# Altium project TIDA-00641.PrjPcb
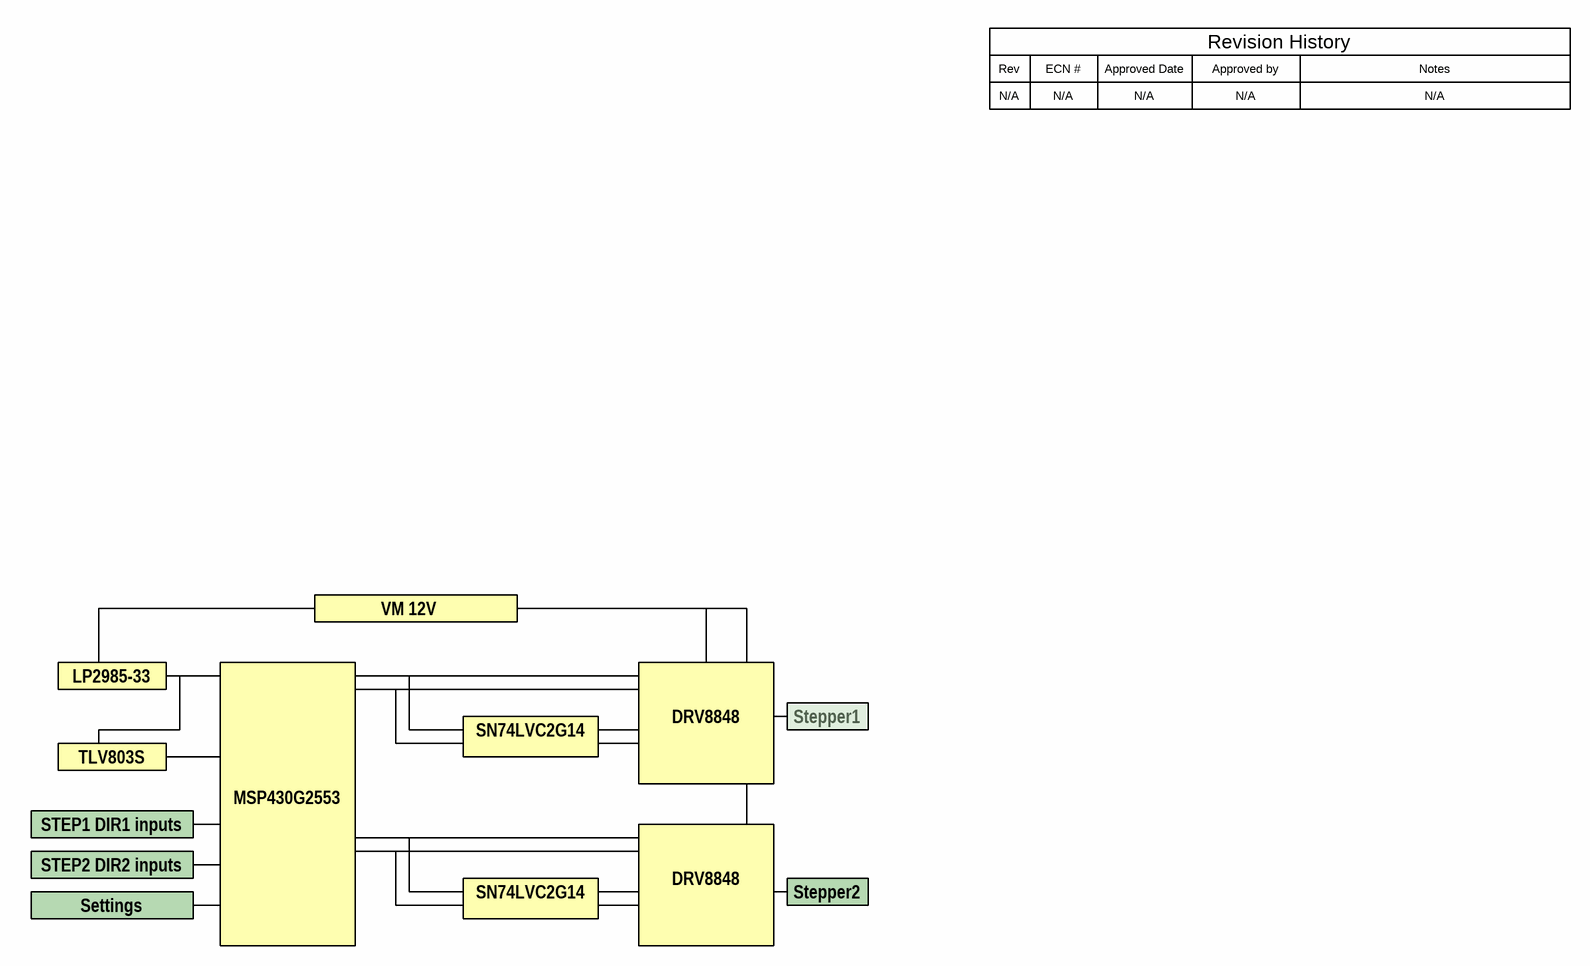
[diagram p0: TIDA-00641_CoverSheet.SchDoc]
CopyrightYear: 2015; EVM_Orderable: N/A; PCB_Layout: Wilson Zuo; PCB_Rev: Rev A; PRJ_Customer: Public Release; PRJ_Engineer: Wilson Zuo; PRJ_Number: TIDA-00641; PRJ_Title: Dual Channels PWM Micro-stepping Module; SCH_Rev: E1; TechSupport: http://www.ti.com/support; TID: 00641
3 sheets, 48 parts. Net scope: global (net labels, ports and power ports of the same name join across sheets).
Board file: TIDA-00641_PCB.PcbDoc
Sheets:
  TIDA-00641_CoverSheet.SchDoc
  TIDA-00641_SCH.SchDoc
  TIDA-00641_Hardware.SchDoc

## Sheet TIDA-00641_CoverSheet.SchDoc
size 431 x 279 mm; Date: Not shown in title block; ApprovedBy: Not shown in title block; CheckedBy: Not shown in title block; Author: Not shown in title block; CompanyName: Not shown in title block; Engineer: Not shown in title block; Organization: Not shown in title block; Address1: Not shown in title block; Address2: Not shown in title block; Address3: Not shown in title block; Address4: Not shown in title block; DocumentNumber: 1; Revision: Use project parameter SCH_Rev; SheetNumber: 1; SheetTotal: 3; PageSetup: Record=PageOptions¦CenterHorizontal=True¦CenterVertical=True¦PrintScale=1.00¦XCorrection=1.00¦YCorrection=1.00¦PrintKind=0¦BorderSize=5000000¦LeftOffset=0¦BottomOffset=0¦Orientation=2¦PaperLength=1000¦PaperWidth=1000¦Scale=100¦PaperSource=15¦PrintQuality=600¦MediaType=1¦DitherType=10¦PaperKind=Letter¦PrintScaleMode=1

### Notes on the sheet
- Rev
- N/A
- ECN #
- Approved Date
- Approved by
- Revision History
- Notes
- VM 12V
- LP2985-33
- TLV803S
- SN74LVC2G14
- DRV8848
- Stepper1
- STEP1 DIR1 inputs
- MSP430G2553
- STEP2 DIR2 inputs
- Settings
- Stepper2

## Sheet TIDA-00641_SCH.SchDoc
size 431 x 279 mm; Date: Not shown in title block; ApprovedBy: Not shown in title block; CheckedBy: Not shown in title block; Author: Not shown in title block; CompanyName: Not shown in title block; Engineer: Not shown in title block; Organization: Not shown in title block; Address1: Not shown in title block; Address2: Not shown in title block; Address3: Not shown in title block; Address4: Not shown in title block; DocumentNumber: 1; Revision: Use project parameter SCH_Rev; SheetNumber: 2; SheetTotal: 3; PageSetup: Record=PageOptions¦CenterHorizontal=True¦CenterVertical=True¦PrintScale=1.00¦XCorrection=1.00¦YCorrection=1.00¦PrintKind=0¦BorderSize=5000000¦LeftOffset=0¦BottomOffset=0¦Orientation=2¦PaperLength=1000¦PaperWidth=1000¦Scale=100¦PaperSource=15¦PrintQuality=600¦MediaType=1¦DitherType=10¦PaperKind=Letter¦PrintScaleMode=1
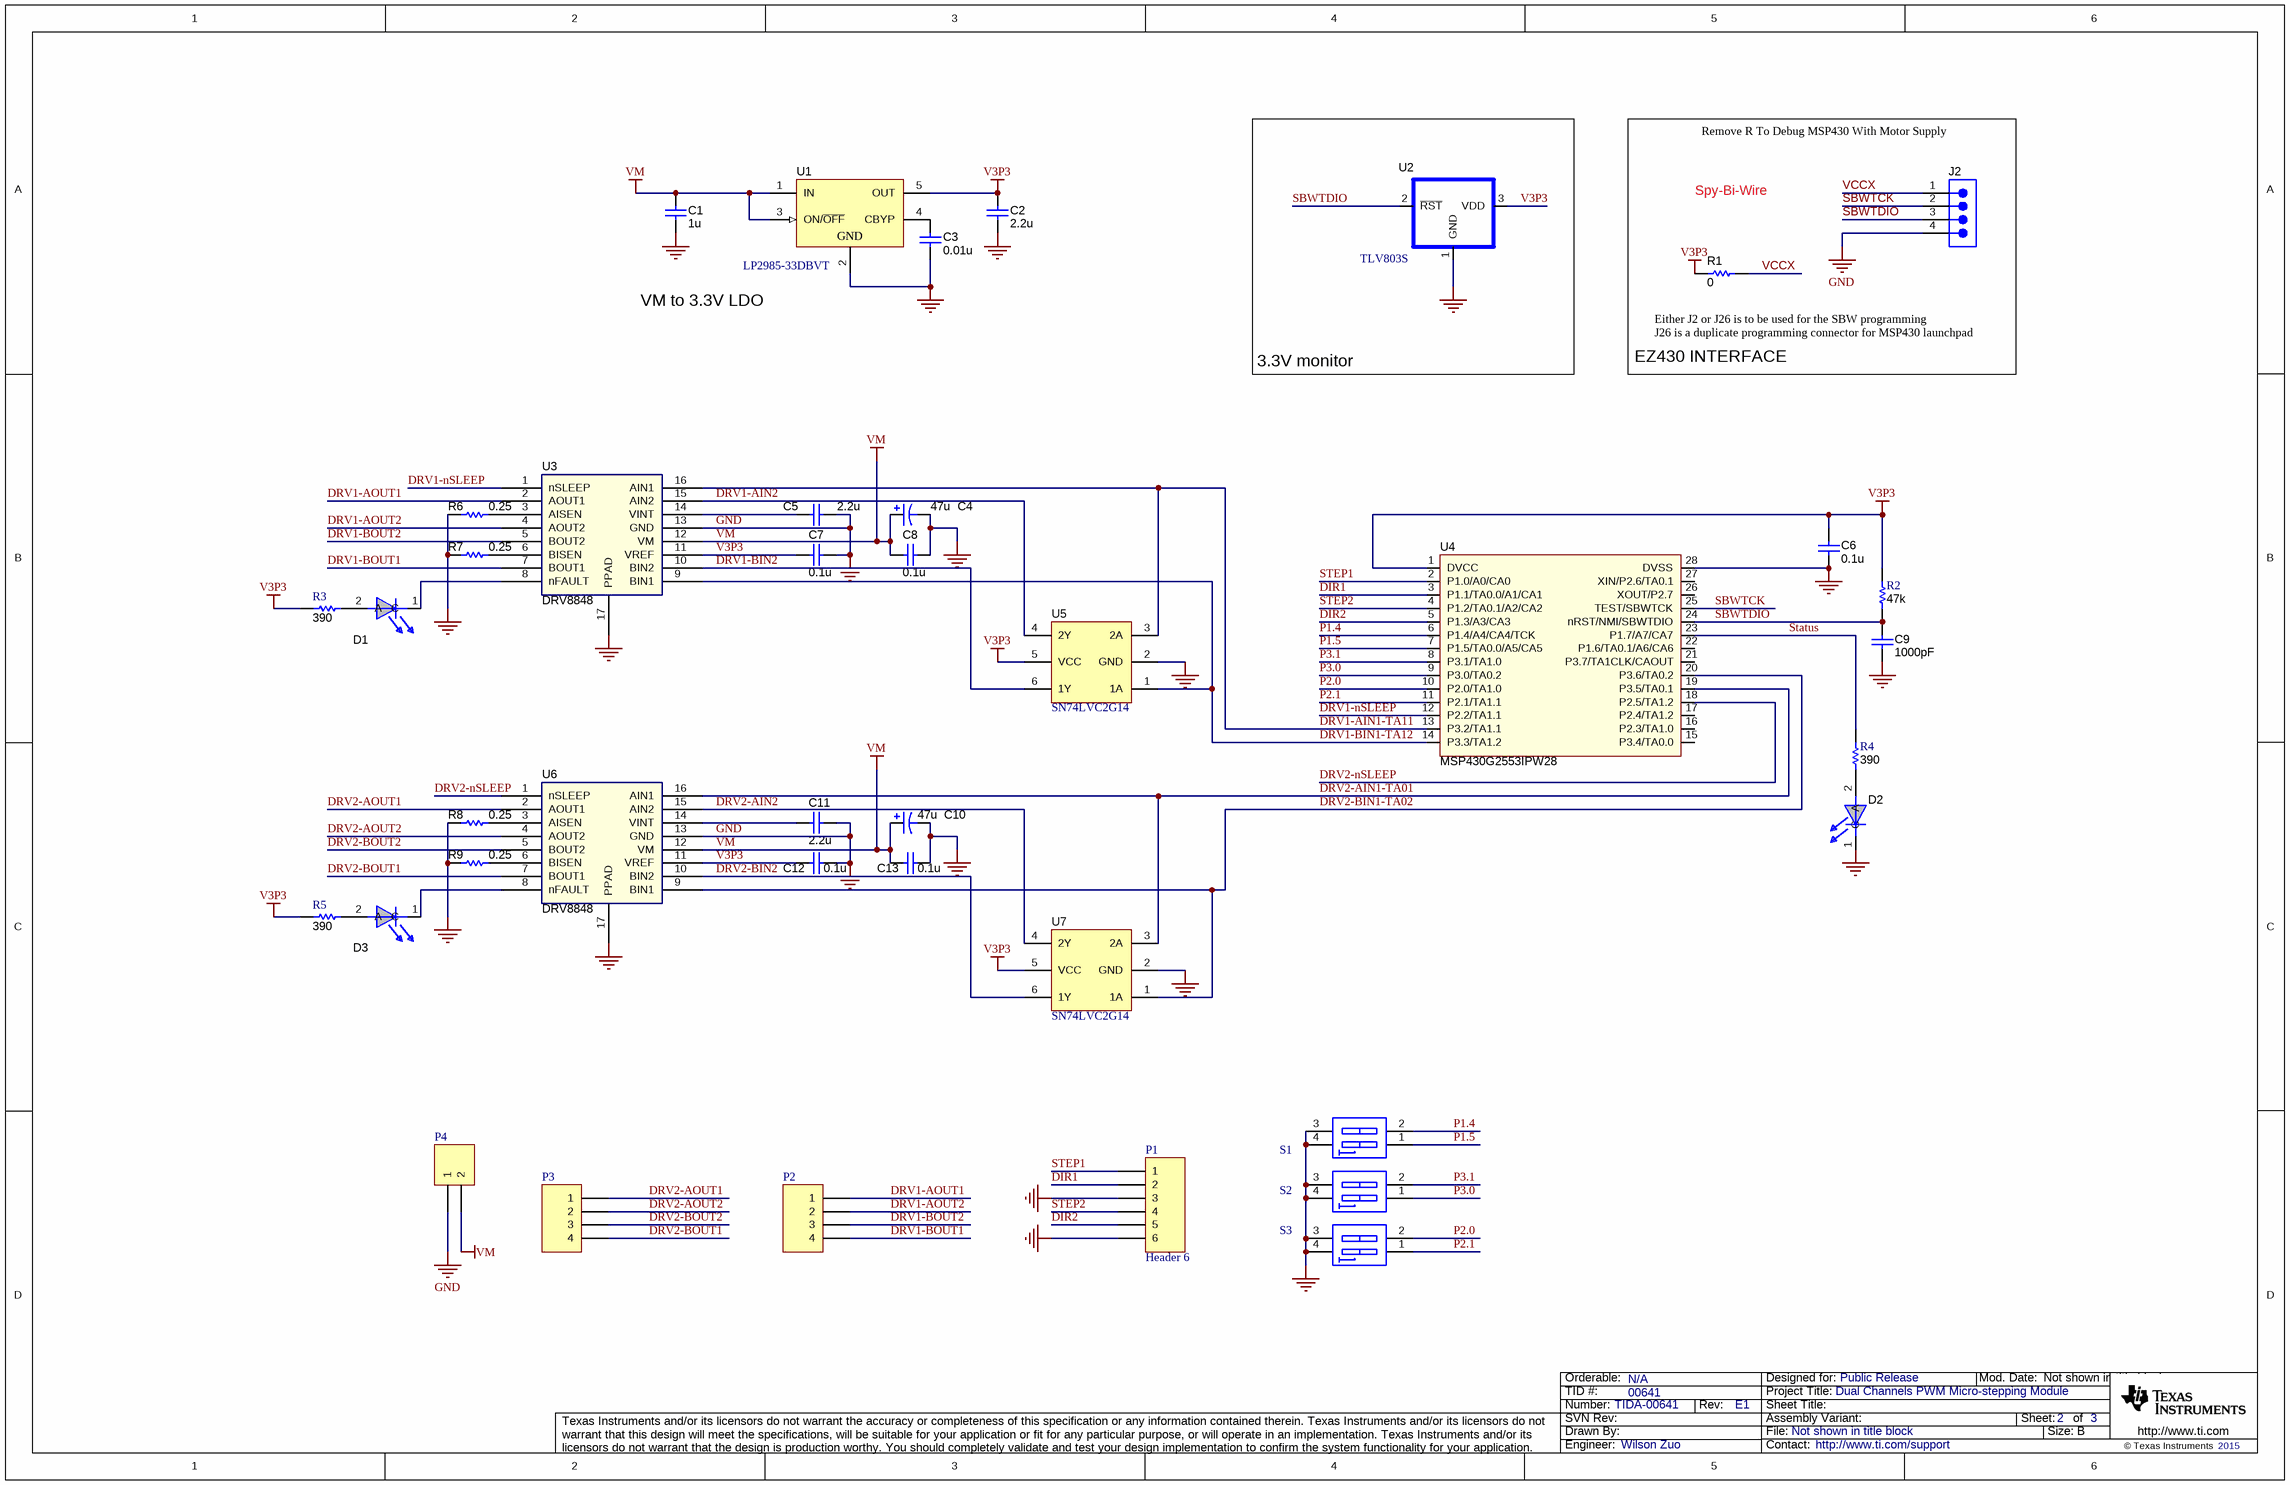
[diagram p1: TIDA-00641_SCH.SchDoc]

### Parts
C1  ValueDisplayed: 1u  [0603L]  (hidden comment: C0603C105K4PACTU)
C2  ValueDisplayed: 2.2u  [0603L]  (hidden comment: C0603C225K8PACTU)
C3  ValueDisplayed: 0.01u  [0603L]  (hidden comment: C0603C103J5RACTU)
C4  ValueDisplayed: 47u  [SM_RADIAL_D]  (hidden comment: EEE-FK1E470P)
C5  ValueDisplayed: 2.2u  [0603L]  (hidden comment: C0603C225M8PACTU)
C6  ValueDisplayed: 0.1u  [0603L]  (hidden comment: C0603C104K4RACTU)
C7  ValueDisplayed: 0.1u  [0603L]  (hidden comment: 06033C104KAT2A)
C8  ValueDisplayed: 0.1u  [0603L]  (hidden comment: 06033C104KAT2A)
C9  ValueDisplayed: 1000pF  [0603L]  (hidden comment: C0603C102K5RACTU)
C10  ValueDisplayed: 47u  [SM_RADIAL_D]  (hidden comment: EEE-FK1E470P)
C11  ValueDisplayed: 2.2u  [0603L]  (hidden comment: C0603C225K8PACTU)
C12  ValueDisplayed: 0.1u  [0603L]  (hidden comment: 06033C104KAT2A)
C13  ValueDisplayed: 0.1u  [0603L]  (hidden comment: 06033C104KAT2A)
D1  LTST-C190KRKT  [LED603RED]  (value not drawn)
D2  LTST-C190GKT  [LED603GRN]  (value not drawn)
D3  LTST-C190KRKT  [LED603RED]  (value not drawn)
J2  TSW-104-07-G-S  [HDR1X4]  (value not drawn)
P1  Header 6  [HDR1X6]
P2  Header 4  [J4-3.81]  (value not drawn)
P3  Header 4  [J4-3.81]  (value not drawn)
P4  Header 2  [j2-3.81]  (value not drawn)
R1  value 0  [0603L]  (hidden comment: ERJ-3GEY0R00V)
R2  value 47k  [0603L]  (hidden comment: CRCW060347K0JNEA)
R3  value 390  [0603L]  (hidden comment: RC0603FR-07390RL)
R4  value 390  [0603L]  (hidden comment: RC0603FR-07390RL)
R5  value 390  [0603L]  (hidden comment: RC0603FR-07390RL)
R6  value 0.25  [2512M]  (hidden comment: CSRN2512FKR250)
R7  value 0.25  [2512M]  (hidden comment: CSRN2512FKR250)
R8  value 0.25  [2512M]  (hidden comment: CSRN2512FKR250)
R9  value 0.25  [2512M]  (hidden comment: CSRN2512FKR250)
S1  SW DIP-2  [DIP-4]  (value not drawn)
S2  SW DIP-2  [DIP-4]  (value not drawn)
S3  SW DIP-2  [DIP-4]  (value not drawn)
U1  LP2985-33DBVT  [MF05A_L]
U2  TLV803S  [SOT-23]
U3  DRV8848  [PW0016S]
U4  MSP430G2553IPW28  [PW0028A_N]
U5  SN74LVC2G14  [DBV0006A_N]
U6  DRV8848  [PW0016S]
U7  SN74LVC2G14  [DBV0006A_N]

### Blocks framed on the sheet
3.3V monitor: U2
EZ430 INTERFACE: J2 R1

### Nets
GND: C1.2 C2.1 C3.2 C4.2(-) C5.2 C6.1 C7.1 C8.1 C9.1 C10.2(-) C11.2 C12.1 C13.1 D2.1(C) J2.4 P1.3 P1.6 P4.1 R6.1 R7.1 R8.1 R9.1 S1.3(B2) S1.4(B1) S2.3(B2) S2.4(B1) S3.3(B2) S3.4(B1) U1.2(GND) U2.1(GND) U3.13(GND) U3.17(PPAD) U4.28(DVSS) U5.2(GND) U6.13(GND) U6.17(PPAD) U7.2(GND)
V3P3: C2.2 C6.2 C7.2 C12.2 R1.1 R2.1 R3.2 R5.2 U1.5(OUT) U2.3(VDD) U3.11(VREF) U4.1(DVCC) U5.5(VCC) U6.11(VREF) U7.5(VCC)
VM: C1.1 C4.1(+) C8.2 C10.1(+) C13.2 P4.2 U1.1(IN) U1.3(ON/~{OFF}) U3.12(VM) U6.12(VM)
DIR1: P1.2 U4.3(P1.1/TA0.0/A1/CA1)
DIR2: P1.5 U4.5(P1.3/A3/CA3)
DRV1-AIN1-TA11: U3.16(AIN1) U4.13(P3.2/TA1.1) U5.3(2A)
DRV1-AIN2: U3.15(AIN2) U5.4(2Y)
DRV1-AOUT1: P2.1 U3.2(AOUT1)
DRV1-AOUT2: P2.2 U3.4(AOUT2)
DRV1-BIN1-TA12: U3.9(BIN1) U4.14(P3.3/TA1.2) U5.1(1A)
DRV1-BIN2: U3.10(BIN2) U5.6(1Y)
DRV1-BOUT1: P2.4 U3.7(BOUT1)
DRV1-BOUT2: P2.3 U3.5(BOUT2)
DRV1-nSLEEP: U3.1(nSLEEP) U4.12(P2.2/TA1.1)
DRV2-AIN1-TA01: U4.19(P3.5/TA0.1) U6.16(AIN1) U7.3(2A)
DRV2-AIN2: U6.15(AIN2) U7.4(2Y)
DRV2-AOUT1: P3.1 U6.2(AOUT1)
DRV2-AOUT2: P3.2 U6.4(AOUT2)
DRV2-BIN1-TA02: U4.20(P3.6/TA0.2) U6.9(BIN1) U7.1(1A)
DRV2-BIN2: U6.10(BIN2) U7.6(1Y)
DRV2-BOUT1: P3.4 U6.7(BOUT1)
DRV2-BOUT2: P3.3 U6.5(BOUT2)
DRV2-nSLEEP: U4.18(P2.5/TA1.2) U6.1(nSLEEP)
P1.4: S1.2(A2) U4.6(P1.4/A4/CA4/TCK)
P1.5: S1.1(A1) U4.7(P1.5/TA0.0/A5/CA5)
P2.0: S3.2(A2) U4.10(P2.0/TA1.0)
P2.1: S3.1(A1) U4.11(P2.1/TA1.1)
P3.0: S2.1(A1) U4.9(P3.0/TA0.2)
P3.1: S2.2(A2) U4.8(P3.1/TA1.0)
SBWTCK: J2.2 U4.25(TEST/SBWTCK)
SBWTDIO: C9.2 J2.3 R2.2 U2.2(~{RST}) U4.24(nRST/NMI/SBWTDIO)
Status: R4.2 U4.23(P1.7/A7/CA7)
STEP1: P1.1 U4.2(P1.0/A0/CA0)
STEP2: P1.4 U4.4(P1.2/TA0.1/A2/CA2)
VCCX: J2.1 R1.2
NetC3_1: C3.1 U1.4(CBYP)
NetC5_1: C5.1 U3.14(VINT)
NetC11_1: C11.1 U6.14(VINT)
NetD1_1: D1.1(C) U3.8(nFAULT)
NetD1_2: D1.2(A) R3.1
NetD2_2: D2.2(A) R4.1
NetD3_1: D3.1(C) U6.8(nFAULT)
NetD3_2: D3.2(A) R5.1
NetR6_2: R6.2 U3.3(AISEN)
NetR7_2: R7.2 U3.6(BISEN)
NetR8_2: R8.2 U6.3(AISEN)
NetR9_2: R9.2 U6.6(BISEN)

Not connected (* = marked no-connect by the designer): U4 15(P3.4/TA0.0) 16(P2.3/TA1.0) 17(P2.4/TA1.2) 21(P3.7/TA1CLK/CAOUT) 22(P1.6/TA0.1/A6/CA6) 26(XOUT/P2.7) 27(XIN/P2.6/TA0.1)

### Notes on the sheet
- Remove R To Debug MSP430 With Motor Supply
- Spy-Bi-Wire
- VM to 3.3V LDO
- (near R1) Either J2 or J26 is to be used for the SBW programming
- J26 is a duplicate programming connector for MSP430 launchpad

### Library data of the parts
C1 = C0603C105K4PACTU: CAP, CERM, 1uF, 16V, +/-10%, X5R, 0603; Manufacturer: Kemet; Polarized: N; CompType: Capacitor; U/M: EA; Cap_F: 0.000001; Tolerance_%: 10; Value1: Unknown; VDC_V: 16; TaMin_C: -55; TaMax_C: 85; Cap_Case: 0603
C2 C11 = C0603C225K8PACTU: CAP, CERM, 2.2uF, 10V, +/-10%, X5R, 0603; Manufacturer: Kemet; Polarized: N; CompType: Capacitor; U/M: EA; Cap_F: 0.0000022; Tolerance_%: 10; Value1: Unknown; TaMin_C: -55; TaMax_C: 85; Cap_Case: 0603
C3 = C0603C103J5RACTU: CAP, CERM, 0.01uF, 50V, +/-5%, X7R, 0603; Manufacturer: Kemet; Polarized: N; CompType: Capacitor; U/M: EA; Cap_F: 0.00000001; Tolerance_%: 5; Value1: Unknown; VDC_V: 50; TaMin_C: -55; TaMax_C: 125; Cap_Case: 0603
C4 C10 = EEE-FK1E470P: CAP, AL, 47uF, 25V, +/-20%, 0.36 ohm, SMD; Manufacturer: Panasonic; Polarized: Y; CompType: Capacitor; U/M: EA; Cap_F: 0.000047; Tolerance_%: 20; ESR_Ohm: 0.36; VDC_V: 25; IRMS_A: 0.24; TaMin_C: -55; TaMax_C: 105; Cap_Case: D
C5 = C0603C225M8PACTU: CAP, CERM, 2.2uF, 10V, +/-20%, X5R, 0603; Manufacturer: Kemet; Polarized: N; CompType: Capacitor; U/M: EA; Cap_F: 0.0000022; Tolerance_%: 20; Value1: Unknown; VDC_V: 10; TaMin_C: -55; TaMax_C: 85; Cap_Case: 0603
C6 = C0603C104K4RACTU: CAP, CERM, 0.1uF, 16V, +/-10%, X7R, 0603; Manufacturer: Kemet; Polarized: N; CompType: Capacitor; U/M: EA; Cap_F: 0.0000001; Tolerance_%: 10; Value1: Unknown; VDC_V: 16; TaMin_C: -55; TaMax_C: 125; Cap_Case: 0603
C7 C8 C12 C13 = 06033C104KAT2A: CAP, CERM, 0.1uF, 25V, +/-10%, X7R, 0603; Manufacturer: AVX; Polarized: N; CompType: Capacitor; U/M: EA; Cap_F: 0.0000001; Tolerance_%: 10; ESR_Ohm: 0.05; Value1: 0.05 ohm; VDC_V: 25; TaMin_C: -55; TaMax_C: 125; Cap_Case: 0603
C9 = C0603C102K5RACTU: CAP, CERM, 1000pF, 50V, +/-10%, X7R, 0603; Manufacturer: Kemet; Polarized: N; CompType: Capacitor; U/M: EA; Cap_F: 0.000000001; Tolerance_%: 10; Value1: Unknown; VDC_V: 50; TaMin_C: -55; TaMax_C: 125; Cap_Case: 0603
D1 D3 = D_LED_603_GRN: LED SUPER RED CLEAR 0603 SMD; Manufacturer: Lite On; Value: LTST-C190GKT; Area: 9451
D2 = D_LED_603_GRN: Diode, LED, Green, 2.1-V, 20-mA, 6-mcd; Manufacturer: Lite On; Area: 9451
J2 = TSW-104-07-G-S: Header, TH, 100mil, 4x1, Gold plated, 230 mil above insulator; Manufacturer: Samtec, Inc.; SymbolCreator: a0412235; U/M: EA
P1 = Header 6: Header, 6-Pin
P2 P3 = Header 4: Header, 4-Pin
P4 = Header 2: Header, 2-Pin
R1 = ERJ-3GEY0R00V: RES, 0 ohm, 5%, 0.1W, 0603; Manufacturer: Panasonic; CompType: Resistor; Value_Code: 0000; Tolerance_%: 5; Power_W: 0.1; VDC_V: 50; TempCo: 600 ppm/C; EIA_Code: E24; U/M: EA
R2 = CRCW060347K0JNEA: RES, 47k ohm, 5%, 0.1W, 0603; Manufacturer: Vishay-Dale; CompType: Resistor; Res_ohm: 47000; Value_Code: 47k0; Tolerance_%: 5; Power_W: 0.1; VDC_V: 75; TempCo: 200 ppm/C; EIA_Code: E24; U/M: EA
R3-R5 = RC0603FR-07390RL: RES, 390 ohm, 1%, 0.1W, 0603; Manufacturer: Yageo America; CompType: Resistor; Value_Code: 390R; Tolerance_%: 1; Power_W: 0.1; VDC_V: 150; TempCo: 200 ppm/C; U/M: EA
R6-R9 = CSRN2512FKR250: RES, 0.25 ohm, 1%, 2W, 2512; Manufacturer: Stackpole Electronics Inc; CompType: Resistor; Value_Code: R250; Tolerance_%: 1; Power_W: 2; TempCo: 200 ppm/C; U/M: EA
S1-S3 = SW DIP-2: SWITCH TIN CONT 2 SEC 50V
U1 = LP2985IM5-3.3: Micropower 150 mA Low-Noise Ultra Low-Dropout Regulator, 5-pin SOT-23; Manufacturer: National Semiconductor; PackageTopMarking: L0RB*XTT; PowerWise: N; CompType: LDO IC
U2 = TLV803DBZ: IC VOLT SUPERVISR 2.93V SOT23-3; Manufacturer: TI; PartNumber: TLV803SDBZR; Alternate Manufacturer: None; Area: 28050; Value: TLV803xDBZ
U3 U6 = DRV8848PWP: IC MOTOR DRIVER PAR 16HTSSOP; Manufacturer: Used in BOM report; Manufacturer: Texas Instruments; SymbolVersion: use current date i.e. 2008-05-20; SymbolCreator: Use a-id; CompType: Used in some BOM reports.  Useful for finding later.; U/M: EA, IN, or GM
U4 = MSP430G2553IPW28: IC MCU 16BIT 16KB FLASH 28TSSOP; Manufacturer: TI; Alternate Manufacturer: None; Area: 92800
U5 U7 = SN74LVC2G14: Dual Schmitt-Trigger Inverter; Manufacturer: Texas Instruments; PartNumber: SN74LVC2G14DBVR

## Sheet TIDA-00641_Hardware.SchDoc
size 431 x 279 mm; Date: Not shown in title block; ApprovedBy: Not shown in title block; CheckedBy: Not shown in title block; Author: Not shown in title block; CompanyName: Not shown in title block; Engineer: Not shown in title block; Organization: Not shown in title block; Address1: Not shown in title block; Address2: Not shown in title block; Address3: Not shown in title block; Address4: Not shown in title block; DocumentNumber: 1; Revision: Use project parameter SCH_Rev; SheetNumber: 3; SheetTotal: 3; PageSetup: Record=PageOptions¦CenterHorizontal=True¦CenterVertical=True¦PrintScale=1.00¦XCorrection=1.00¦YCorrection=1.00¦PrintKind=0¦BorderSize=5000000¦LeftOffset=0¦BottomOffset=0¦Orientation=2¦PaperLength=1000¦PaperWidth=1000¦Scale=100¦PaperSource=15¦PrintQuality=600¦MediaType=1¦DitherType=10¦PaperKind=Letter¦PrintScaleMode=1
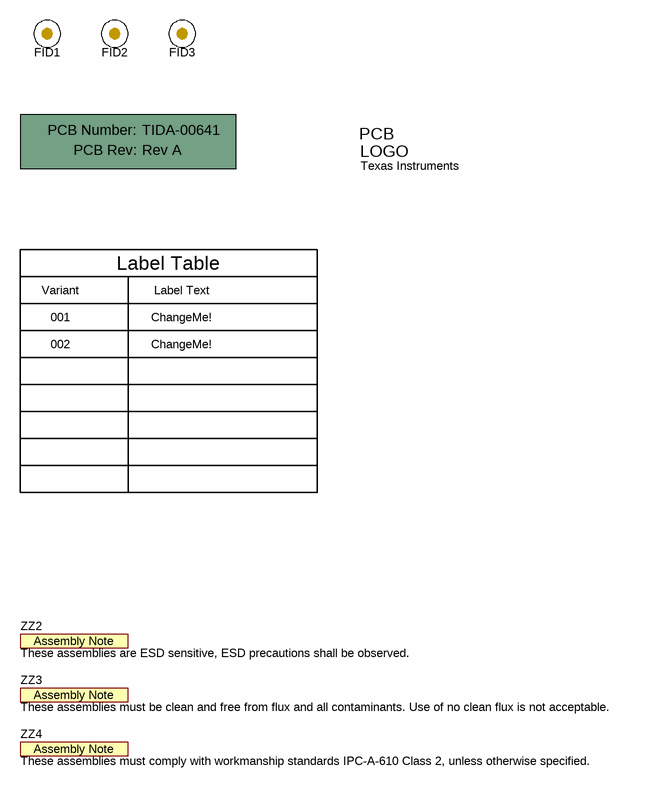
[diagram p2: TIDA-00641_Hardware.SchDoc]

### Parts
!PCB  Printed Circuit Board  (value not drawn)  (mechanical)
FID1  Fiducial  [Fiducial10-20]  (value not drawn)
FID2  Fiducial  [Fiducial10-20]  (value not drawn)
FID3  Fiducial  [Fiducial10-20]  (value not drawn)
Logo1  Texas Instruments  [TI_Stacked_Overlay_Small]  (no BOM)
ZZ2  These assemblies are ESD sensitive, ESD precautions shall be observed.  [AssemblyNote]  (no BOM)
ZZ3  These assemblies must be clean and free from flux and all contaminants. Use of no clean flux is not acceptable.  [AssemblyNote]  (no BOM)
ZZ4  These assemblies must comply with workmanship standards IPC-A-610 Class 2, unless otherwise specified.  [AssemblyNote]  (no BOM)

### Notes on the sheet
- Variant
- Label Table
- Label Text
- 001
- 002
- ChangeMe!

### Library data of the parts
!PCB = PCB: Manufacturer: Any; PartNumber: TIDA-00641; SymbolCreator: a0412235
FID1-FID3 = Fiducial: Fiducial mark.  There is nothing to buy or mount.; SymbolCreator: codlsc
Logo1 = TI_Logo: Texas Instrument Corporate Signature; SymbolCreator: codlsc
ZZ2-ZZ4 = AssemblyNote: SymbolCreator: codlsc

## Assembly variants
001: not fitted FID1 FID2 FID3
